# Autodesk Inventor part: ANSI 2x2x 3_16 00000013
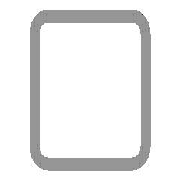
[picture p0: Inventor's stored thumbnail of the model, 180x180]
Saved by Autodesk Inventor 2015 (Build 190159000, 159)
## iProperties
_FrameMemberDoc: Frame Member File
_Version: 15.0.0
_CCFamilyMember: 1
_CCFamilyDisplayName: ANSI AISC (Square) - Tube
Created: 2007-02
Part Number: ANSI 2x2x 3_16 00000013
Material: Steel
Document SubType Name: Modeling
Standard: AISC
Designer: Autodesk, Inc.
Size Designation: 2x2x3/16
Stock Number: 2x2x 3/16
Density: 7.85 g/cm^3
Description: Tube
Standards Organization: ANSI
Language: en-US
Categories: <MemberInstance><Categories><Category DisplayName="Structural Shapes" InternalName="089c4875-fa83-4c05-b084-43b9cc11f5ed" Mnemonic="GRDR"><CategoryParameter Dis
Mass: 6931.14 g
Surface Area: 3724.29 cm^2
Volume: 882.948 cm^3
Appearance: Steel
IsCustomPart: 1
G_L: 42.465 in
G_W: 2.000 in
G_H: 2.000 in
+EEF3F901-C0C6-443E-BF16-2057D9D3800C+CUTDETAIL1: Cut
+E01EF069-5206-4835-A24F-C3618286411A+CUTDETAIL2: Cut
Author: Autodesk, Inc.
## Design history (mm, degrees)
node "Start plane"
node "End plane"
sketch "Sketch"
  geometry: L1 (-25.4, -15.875)-(-25.4, 15.875); L2 (-15.875, 25.4)-(15.875, 25.4); L3 (25.4, 15.875)-(25.4, -15.875); L4 (15.875, -25.4)-(-15.875, -25.4); L5 (-15.875, 20.637)-(15.875, 20.638); L6 (20.637, 15.875)-(20.637, -15.875); L7 (15.875, -20.637)-(-15.875, -20.638); L8 (-20.637, -15.875)-(-20.637, 15.875); L9 (0, 38.322)-(0, -38.322) reference; L10 (-38.322, 0)-(38.322, 0) reference; A1 r 9.525 centre (-15.875, -15.875) between (-25.4, -15.875) and (-15.875, -25.4); A2 r 9.525 centre (-15.875, 15.875) between (-15.875, 25.4) and (-25.4, 15.875); A3 r 9.525 centre (15.875, 15.875) between (25.4, 15.875) and (15.875, 25.4); A4 r 9.525 centre (15.875, -15.875) between (15.875, -25.4) and (25.4, -15.875); A5 r 4.762 centre (-15.875, 15.875) between (-15.875, 20.637) and (-20.637, 15.875); A6 r 4.762 centre (15.875, 15.875) between (20.637, 15.875) and (15.875, 20.638); A7 r 4.762 centre (15.875, -15.875) between (15.875, -20.637) and (20.637, -15.875); A8 r 4.762 centre (-15.875, -15.875) between (-20.637, -15.875) and (-15.875, -20.638)
  constraints: 16 end point, 16 point on circle, 8 centre point, 8 tangent, 4 parallel, 3 equal radius, 2 perpendicular, 7 other
  dimensions: "d10" = 50.8 distance between parallel lines of L2 L4 (= G_H); "d11" = 50.8 distance between parallel lines of L1 L3 (= G_W); "d12" = 4.7625 distance between parallel lines of L3 L6 (= G_T); "d15" = 25.4 distance between parallel lines of L2 L10 (= 0.5 x d10); "d16" = 25.4 distance between parallel lines of L9 L3 (= 0.5 x d11); "d17" = 9.525 radius of A1 (= G_IR)
extrude "Body" new body sketch "Sketch" stored distance "d3" = 1078.6 (= G_L); taper "d4" = 0 deg
node "Driven Length"
  sketch "Sketch3"
    geometry: L1 (0, 0)-(10, 0) reference
    constraints: 2 end point, 1 horizontal
  workplane "Work Plane5"
  sketch "Sketch4"
    geometry: L1 (-2, -603.614)-(12, -603.614) reference; L2 (-2, 474.986)-(12, 474.986) reference
    dimensions: "d19" = 1078.6 distance between parallel lines of L1 L2 (derived)
workplane "Work Plane3"
split "Split1"
workplane "Work Plane4"
split "Split2"
body "Solid1"
other parameters: "G_W" = 50.8 [user parameter; used in 1 equation term], "G_H" = 50.8 [user parameter; used in 1 equation term], "G_T" = 4.7625 [user parameter; used in 1 equation term], "G_IR" = 9.525 [user parameter; used in 1 equation term], "G_L" = 1078.6 (= d19) [user parameter; used in 1 equation term], "G_OFFSET_START" = 603.61418 [user parameter; used in 1 equation term], "G_OFFSET_END" = 183.00326 [user parameter; used in 1 equation term], "d13" = -603.61418 (= -G_OFFSET_START), "d14" = 474.98582 (= G_OFFSET_END + B_L), "B_L" = 291.98256 [user parameter; used in 1 equation term], "d18" = 90 deg
